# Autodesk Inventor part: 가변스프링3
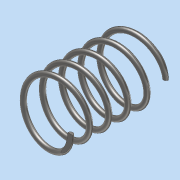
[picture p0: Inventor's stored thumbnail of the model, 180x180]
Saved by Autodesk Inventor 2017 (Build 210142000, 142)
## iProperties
Part Number: 가변스프링3
Material: 강철, 연강
Document SubType Name: Modeling
Designer: MRC
Density: 7.85 g/cm^3
Appearance: 반연마
Mass: 8.42454 g
Surface Area: 21.7273 cm^2
Volume: 1.07319 cm^3
Author: MRC
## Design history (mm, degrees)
sketch "스케치1"
  geometry: L1 (0, 0)-(0, 37.411); L2 (0, 0)-(11, 0); L3 (0, 37.411)-(11, 37.411); C1 r 1 at (11, 0)
  constraints: 6 end point, 2 horizontal, 1 centre point, 1 coincident, 1 vertical
  dimensions: "d0" = 11 distance of L1.start L2.end; "d1" = 11 distance of L1.end L3.end; "d2" = 2 diameter of C1; "d3" = 37.4112 distance of L1.start L1.end (derived)
feature "코일1" sketch "스케치1" pitch "d4" = 10; turns "d6" = 5; dims "d5" = 37.4112 (= d3), "d7" = 0, angle "d8" = 90 deg, angle "d9" = 90 deg, "d10" = 0, "d11" = 0
sketch "스케치2"
  geometry: L1 (37.411, 20)-(0, 20); L2 (0, 20)-(0, -20); L3 (0, -20)-(37.411, -20); L4 (37.411, -20)-(37.411, 20); 2 further points
  constraints: 8 end point, 2 parallel, 1 coincident, 1 horizontal, 1 midpoint, 1 perpendicular
  dimensions: "d13" = 37.4112 distance of L2.end L3.end (= d3); "d14" = 40 distance of L3.end L1.start
extrude "돌출1" sketch "스케치2" stored distance "d15" = 0; taper "d16" = 0 deg
node "솔리드1"
